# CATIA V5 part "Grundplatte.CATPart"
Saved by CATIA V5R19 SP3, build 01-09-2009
Part number: Deckplatte
Bounding box of the stored display mesh (mm): x -92.49 to 92.49, y -92.5 to 92.5, z -121.345 to 141.345
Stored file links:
  C:\Users\Timo\Desktop\Hexapod\Grundplatte.CATPart
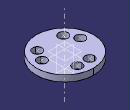
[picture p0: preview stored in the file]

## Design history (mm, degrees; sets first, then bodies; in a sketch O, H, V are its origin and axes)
Set1
  Plane1: type Offset, RefPlane xy-plane, Offset 20
  AxisLine1: Element face of Pad1 from Sketch1.A1
  Point1: type Center, Curve edge [end face of Pad1 | face of CircPattern1]
  Point2: type Center, Curve edge [end face of Pad1 | face of CircPattern1]
  Point3: type Center, Curve edge [end face of Pad1 | face of Pocket1 from Sketch2.A1]
  Point4: type Center, Curve edge [end face of Pad1 | face of Pocket1 from Sketch2.A2]
  Point5: type Center, Curve edge [end face of Pad1 | face of CircPattern1]
  Point6: type Center, Curve edge [end face of Pad1 | face of CircPattern1]
Body1 (main body)
  Sketch1 on xy-plane, origin (0, 0, 0), H (0, 1, 0), V (-1, 0, 0)
    circle A1 centre (0, 0) radius 92.5
    radius A1 = 92.5
  Pad1: profile Sketch1, direction (0, 0, 1), length 20
  Sketch2 on Plane1, origin (0, 0, 20), H (-1, 0, 0), V (0, -1, 0)
    circle A1 centre (20, -60) radius 15
    point P1 (20, -60)
    circle A2 centre (-20, -60) radius 15
    point P2 (-20, -60)
    reference intersected line E1 through (0, 0) direction (0, -1) from yz-plane
    reference intersected line E2 through (0, 0) direction (1, 0) from zx-plane
    reference intersected line E3 through (0, 0) direction (0, -1) from yz-plane
    reference intersected line E4 through (0, 0) direction (1, 0) from zx-plane
    radius A2 = 15
    radius A1 = 15
    distance P2 E1 = 20
    distance E2 P1 = 60
    distance E3 P1 = 20
    distance E4 P2 = 60
  Pocket1: profile Sketch2, direction (0, 0, -1), length 30
  CircPattern1: of Pocket1, instances 3, angular step 120, axis from AxisLine1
